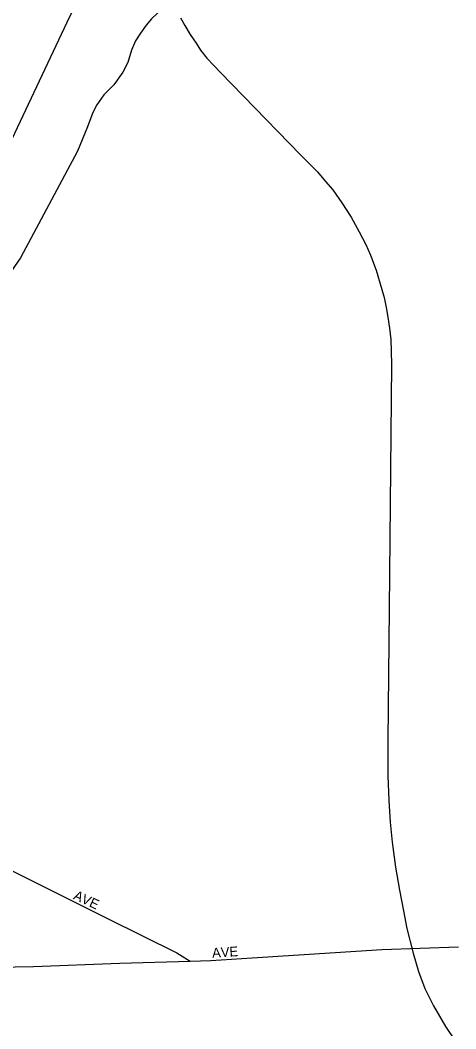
# Model space of a CAD drawing. Extents: x -561 to 1170, y 0 to 846.
# Drawn here: x 252.21 to 258.24, y 237.01 to 250.97 of the extents above; entities that cross this region are included whole.
import ezdxf

# ---------------------------------------------------------------- set-up
doc = ezdxf.new("R2010")
doc.units = 0
for name, color, linetype in [('GM_X_City_Street', 7, 'Continuous'), ('GM_X_City_Street_Text', 7, 'Continuous'), ('GM_X_Rail_Line', 7, 'Continuous')]:
    doc.layers.add(name, color=color, linetype=linetype)

msp = doc.modelspace()

# ---------------------------------------------------------------- linework, layer by layer
at = {"layer": 'GM_X_City_Street'}
for points in [[(251.75, 239.366), (253.418, 238.535)], [(253.418, 238.535), (254.378, 238.058), (254.563, 237.942)], [(255.421, 237.989), (257.218, 238.103), (258.279, 238.141)], [(254.849, 237.952), (255.421, 237.989)], [(250.577, 237.833), (250.592, 237.833), (251.106, 237.844), (252.392, 237.87), (253.586, 237.916), (254.563, 237.942)], [(254.563, 237.942), (254.849, 237.952), (254.849, 237.952)]]:
    msp.add_lwpolyline(points, dxfattribs=at)
at = {"layer": 'GM_X_Rail_Line'}
for points in [[(249.965, 244.988), (250.527, 246.012), (252.857, 250.943), (253.84, 252.977), (254.042, 253.54), (254.461, 254.984), (254.779, 255.793), (255.111, 256.717), (255.414, 257.367), (255.731, 258.133), (256.035, 258.782), (256.367, 259.49), (256.319, 260.503)], [(254.324, 251.217), (254.21, 251.142), (254.107, 251.068), (254.024, 250.99), (253.95, 250.904), (253.871, 250.79), (253.802, 250.687), (253.748, 250.555), (253.699, 250.386), (253.627, 250.253), (253.506, 250.078), (253.367, 249.936), (253.267, 249.801), (253.212, 249.691), (253.14, 249.495), (253.001, 249.16), (252.213, 247.679), (251.547, 246.725), (250.659, 245.659), (249.965, 244.988)], [(254.428, 251.002), (254.487, 250.899), (254.561, 250.773), (254.643, 250.652), (254.703, 250.555), (254.792, 250.447), (254.891, 250.342), (254.981, 250.245), (256.091, 249.107), (256.205, 248.993), (256.323, 248.872), (256.437, 248.74), (256.536, 248.622), (256.664, 248.442), (256.79, 248.246), (256.904, 248.042), (256.995, 247.865), (257.06, 247.716), (257.137, 247.512), (257.194, 247.323), (257.246, 247.131), (257.277, 246.994), (257.299, 246.858), (257.324, 246.709), (257.339, 246.551), (257.346, 246.39), (257.351, 246.206), (257.318, 242.821), (257.298, 240.996), (257.298, 240.509), (257.311, 240.168), (257.33, 239.868), (257.358, 239.591), (257.405, 239.245), (257.459, 238.926), (257.514, 238.641), (257.564, 238.396), (257.651, 238.052), (257.724, 237.799), (257.812, 237.567), (257.93, 237.324), (258.098, 237.037), (258.233, 236.838)]]:
    msp.add_lwpolyline(points, dxfattribs=at)

# ---------------------------------------------------------------- texts
at = {"layer": 'GM_X_City_Street_Text'}
for rotation, p in [(335.2307, (252.933, 238.807)), (3.9506, (254.869, 237.989))]:
    msp.add_text('AVE', height=0.135, rotation=rotation, dxfattribs=at).set_placement(p)

doc.saveas('drawing.dxf')
